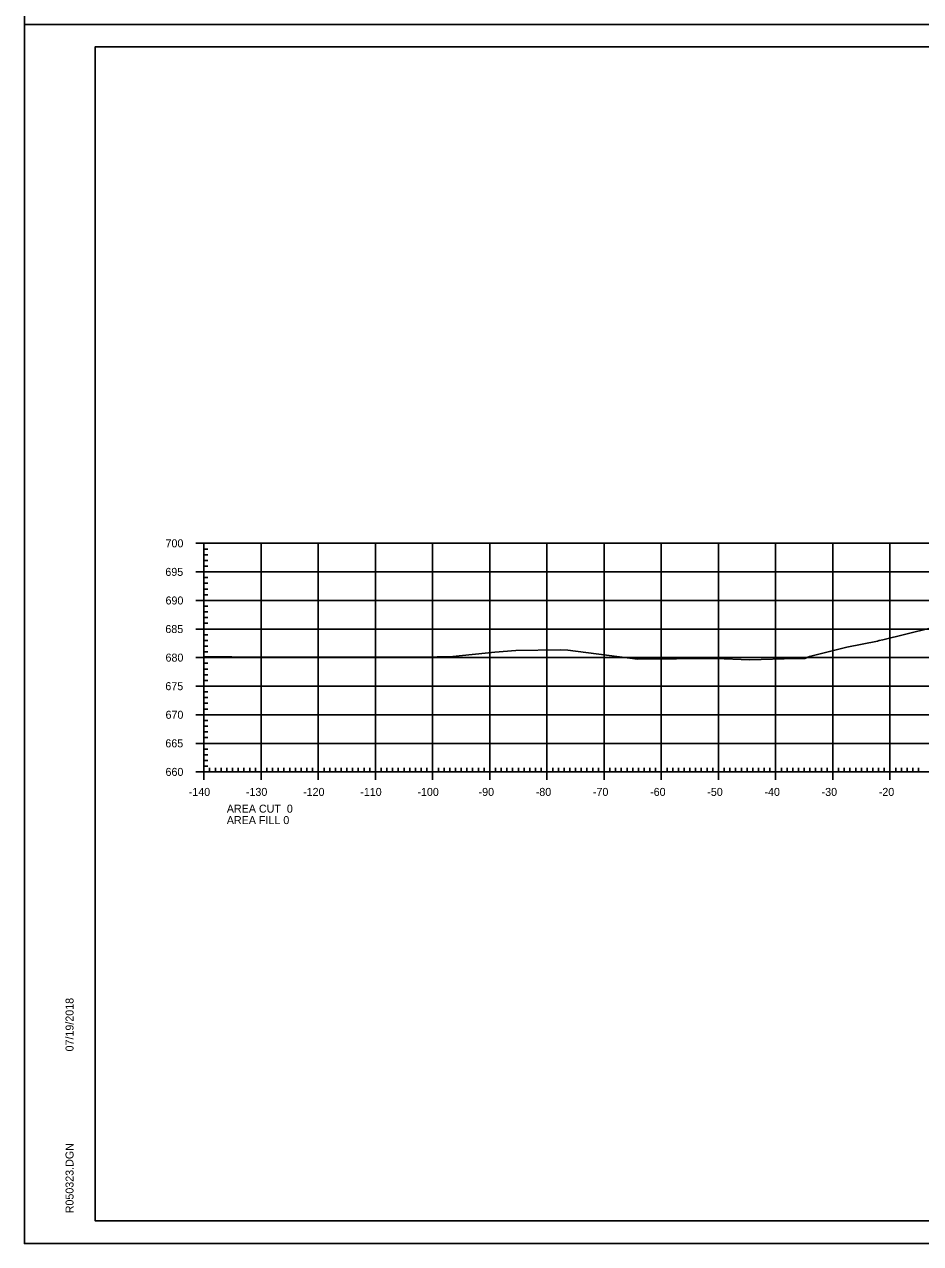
# Model space of a CAD drawing. Extents: x 1360146 to 1361431, y 631444 to 632352.
# Drawn here: x 1360146.4 to 1360303.1, y 631444.2 to 631657.5 of the extents above; entities that cross this region are included whole.
import ezdxf

# ---------------------------------------------------------------- set-up
doc = ezdxf.new("R2010")
doc.units = 0
for name, color, linetype in [('R_Axis', 7, 'Continuous'), ('R_Axis Annot', 7, 'Continuous'), ('R_Border', 7, 'Continuous'), ('R_Exist Surface', 7, 'Continuous'), ('R_Grid', 7, 'Continuous'), ('R_No Plot', 7, 'Continuous')]:
    doc.layers.add(name, color=color, linetype=linetype)

msp = doc.modelspace()

# ---------------------------------------------------------------- linework, layer by layer
at = {"layer": 'R_Axis'}
for p, q in [((1360176.37, 631566.7), (1360177.77, 631566.7)), ((1360177.77, 631526.7), (1360177.77, 631566.7)), ((1360177.77, 631565.7), (1360178.47, 631565.7)), ((1360177.77, 631564.7), (1360178.47, 631564.7)), ((1360177.77, 631563.7), (1360178.47, 631563.7)), ((1360177.77, 631562.7), (1360178.47, 631562.7)), ((1360176.37, 631561.7), (1360177.77, 631561.7)), ((1360177.77, 631560.7), (1360178.47, 631560.7)), ((1360177.77, 631559.7), (1360178.47, 631559.7)), ((1360177.77, 631558.7), (1360178.47, 631558.7)), ((1360176.37, 631556.7), (1360177.77, 631556.7)), ((1360177.77, 631557.7), (1360178.47, 631557.7)), ((1360177.77, 631555.7), (1360178.47, 631555.7)), ((1360177.77, 631554.7), (1360178.47, 631554.7)), ((1360177.77, 631553.7), (1360178.47, 631553.7)), ((1360177.77, 631552.7), (1360178.47, 631552.7)), ((1360176.37, 631551.7), (1360177.77, 631551.7)), ((1360177.77, 631550.7), (1360178.47, 631550.7)), ((1360177.77, 631549.7), (1360178.47, 631549.7)), ((1360177.77, 631548.7), (1360178.47, 631548.7)), ((1360177.77, 631547.7), (1360178.47, 631547.7)), ((1360176.37, 631546.7), (1360177.77, 631546.7)), ((1360177.77, 631545.7), (1360178.47, 631545.7)), ((1360177.77, 631544.7), (1360178.47, 631544.7)), ((1360177.77, 631543.7), (1360178.47, 631543.7)), ((1360176.37, 631541.7), (1360177.77, 631541.7)), ((1360177.77, 631542.7), (1360178.47, 631542.7)), ((1360177.77, 631540.7), (1360178.47, 631540.7)), ((1360177.77, 631539.7), (1360178.47, 631539.7)), ((1360177.77, 631538.7), (1360178.47, 631538.7)), ((1360177.77, 631537.7), (1360178.47, 631537.7)), ((1360176.37, 631536.7), (1360177.77, 631536.7)), ((1360177.77, 631535.7), (1360178.47, 631535.7)), ((1360177.77, 631534.7), (1360178.47, 631534.7)), ((1360177.77, 631533.7), (1360178.47, 631533.7)), ((1360177.77, 631532.7), (1360178.47, 631532.7)), ((1360176.37, 631531.7), (1360177.77, 631531.7)), ((1360177.77, 631530.7), (1360178.47, 631530.7)), ((1360177.77, 631529.7), (1360178.47, 631529.7)), ((1360177.77, 631528.7), (1360178.47, 631528.7)), ((1360176.37, 631526.7), (1360177.77, 631526.7)), ((1360177.77, 631527.7), (1360178.47, 631527.7)), ((1360177.77, 631526.7), (1360457.77, 631526.7)), ((1360177.77, 631525.3), (1360177.77, 631526.7)), ((1360178.77, 631526.7), (1360178.77, 631527.4)), ((1360179.77, 631526.7), (1360179.77, 631527.4)), ((1360180.77, 631526.7), (1360180.77, 631527.4)), ((1360181.77, 631526.7), (1360181.77, 631527.4)), ((1360182.77, 631526.7), (1360182.77, 631527.4)), ((1360183.77, 631526.7), (1360183.77, 631527.4)), ((1360184.77, 631526.7), (1360184.77, 631527.4)), ((1360185.77, 631526.7), (1360185.77, 631527.4)), ((1360186.77, 631526.7), (1360186.77, 631527.4)), ((1360187.77, 631525.3), (1360187.77, 631526.7)), ((1360188.77, 631526.7), (1360188.77, 631527.4)), ((1360189.77, 631526.7), (1360189.77, 631527.4)), ((1360190.77, 631526.7), (1360190.77, 631527.4)), ((1360191.77, 631526.7), (1360191.77, 631527.4)), ((1360192.77, 631526.7), (1360192.77, 631527.4)), ((1360193.77, 631526.7), (1360193.77, 631527.4)), ((1360194.77, 631526.7), (1360194.77, 631527.4)), ((1360195.77, 631526.7), (1360195.77, 631527.4)), ((1360196.77, 631526.7), (1360196.77, 631527.4)), ((1360197.77, 631525.3), (1360197.77, 631526.7)), ((1360198.77, 631526.7), (1360198.77, 631527.4)), ((1360199.77, 631526.7), (1360199.77, 631527.4)), ((1360200.77, 631526.7), (1360200.77, 631527.4)), ((1360201.77, 631526.7), (1360201.77, 631527.4)), ((1360202.77, 631526.7), (1360202.77, 631527.4)), ((1360203.77, 631526.7), (1360203.77, 631527.4)), ((1360204.77, 631526.7), (1360204.77, 631527.4)), ((1360205.77, 631526.7), (1360205.77, 631527.4)), ((1360206.77, 631526.7), (1360206.77, 631527.4)), ((1360207.77, 631525.3), (1360207.77, 631526.7)), ((1360208.77, 631526.7), (1360208.77, 631527.4)), ((1360209.77, 631526.7), (1360209.77, 631527.4)), ((1360210.77, 631526.7), (1360210.77, 631527.4)), ((1360211.77, 631526.7), (1360211.77, 631527.4)), ((1360212.77, 631526.7), (1360212.77, 631527.4)), ((1360213.77, 631526.7), (1360213.77, 631527.4)), ((1360214.77, 631526.7), (1360214.77, 631527.4)), ((1360215.77, 631526.7), (1360215.77, 631527.4)), ((1360216.77, 631526.7), (1360216.77, 631527.4)), ((1360217.77, 631525.3), (1360217.77, 631526.7)), ((1360218.77, 631526.7), (1360218.77, 631527.4)), ((1360219.77, 631526.7), (1360219.77, 631527.4)), ((1360220.77, 631526.7), (1360220.77, 631527.4)), ((1360221.77, 631526.7), (1360221.77, 631527.4)), ((1360222.77, 631526.7), (1360222.77, 631527.4)), ((1360223.77, 631526.7), (1360223.77, 631527.4)), ((1360224.77, 631526.7), (1360224.77, 631527.4)), ((1360225.77, 631526.7), (1360225.77, 631527.4)), ((1360226.77, 631526.7), (1360226.77, 631527.4)), ((1360227.77, 631525.3), (1360227.77, 631526.7)), ((1360228.77, 631526.7), (1360228.77, 631527.4)), ((1360229.77, 631526.7), (1360229.77, 631527.4)), ((1360230.77, 631526.7), (1360230.77, 631527.4)), ((1360231.77, 631526.7), (1360231.77, 631527.4)), ((1360232.77, 631526.7), (1360232.77, 631527.4)), ((1360233.77, 631526.7), (1360233.77, 631527.4)), ((1360234.77, 631526.7), (1360234.77, 631527.4)), ((1360235.77, 631526.7), (1360235.77, 631527.4)), ((1360236.77, 631526.7), (1360236.77, 631527.4)), ((1360237.77, 631525.3), (1360237.77, 631526.7)), ((1360238.77, 631526.7), (1360238.77, 631527.4)), ((1360239.77, 631526.7), (1360239.77, 631527.4)), ((1360240.77, 631526.7), (1360240.77, 631527.4)), ((1360241.77, 631526.7), (1360241.77, 631527.4)), ((1360242.77, 631526.7), (1360242.77, 631527.4)), ((1360243.77, 631526.7), (1360243.77, 631527.4)), ((1360244.77, 631526.7), (1360244.77, 631527.4)), ((1360245.77, 631526.7), (1360245.77, 631527.4)), ((1360246.77, 631526.7), (1360246.77, 631527.4)), ((1360247.77, 631525.3), (1360247.77, 631526.7)), ((1360248.77, 631526.7), (1360248.77, 631527.4)), ((1360249.77, 631526.7), (1360249.77, 631527.4)), ((1360250.77, 631526.7), (1360250.77, 631527.4)), ((1360251.77, 631526.7), (1360251.77, 631527.4)), ((1360252.77, 631526.7), (1360252.77, 631527.4)), ((1360253.77, 631526.7), (1360253.77, 631527.4)), ((1360254.77, 631526.7), (1360254.77, 631527.4)), ((1360255.77, 631526.7), (1360255.77, 631527.4)), ((1360256.77, 631526.7), (1360256.77, 631527.4)), ((1360257.77, 631525.3), (1360257.77, 631526.7)), ((1360258.77, 631526.7), (1360258.77, 631527.4)), ((1360259.77, 631526.7), (1360259.77, 631527.4)), ((1360260.77, 631526.7), (1360260.77, 631527.4)), ((1360261.77, 631526.7), (1360261.77, 631527.4)), ((1360262.77, 631526.7), (1360262.77, 631527.4)), ((1360263.77, 631526.7), (1360263.77, 631527.4)), ((1360264.77, 631526.7), (1360264.77, 631527.4)), ((1360265.77, 631526.7), (1360265.77, 631527.4)), ((1360266.77, 631526.7), (1360266.77, 631527.4)), ((1360267.77, 631525.3), (1360267.77, 631526.7)), ((1360268.77, 631526.7), (1360268.77, 631527.4)), ((1360269.77, 631526.7), (1360269.77, 631527.4)), ((1360270.77, 631526.7), (1360270.77, 631527.4)), ((1360271.77, 631526.7), (1360271.77, 631527.4)), ((1360272.77, 631526.7), (1360272.77, 631527.4)), ((1360273.77, 631526.7), (1360273.77, 631527.4)), ((1360274.77, 631526.7), (1360274.77, 631527.4)), ((1360275.77, 631526.7), (1360275.77, 631527.4)), ((1360276.77, 631526.7), (1360276.77, 631527.4)), ((1360277.77, 631525.3), (1360277.77, 631526.7)), ((1360278.77, 631526.7), (1360278.77, 631527.4)), ((1360279.77, 631526.7), (1360279.77, 631527.4)), ((1360280.77, 631526.7), (1360280.77, 631527.4)), ((1360281.77, 631526.7), (1360281.77, 631527.4)), ((1360282.77, 631526.7), (1360282.77, 631527.4)), ((1360283.77, 631526.7), (1360283.77, 631527.4)), ((1360284.77, 631526.7), (1360284.77, 631527.4)), ((1360285.77, 631526.7), (1360285.77, 631527.4)), ((1360286.77, 631526.7), (1360286.77, 631527.4)), ((1360287.77, 631525.3), (1360287.77, 631526.7)), ((1360288.77, 631526.7), (1360288.77, 631527.4)), ((1360289.77, 631526.7), (1360289.77, 631527.4)), ((1360290.77, 631526.7), (1360290.77, 631527.4)), ((1360291.77, 631526.7), (1360291.77, 631527.4)), ((1360292.77, 631526.7), (1360292.77, 631527.4)), ((1360293.77, 631526.7), (1360293.77, 631527.4)), ((1360294.77, 631526.7), (1360294.77, 631527.4)), ((1360295.77, 631526.7), (1360295.77, 631527.4)), ((1360296.77, 631526.7), (1360296.77, 631527.4)), ((1360297.77, 631525.3), (1360297.77, 631526.7)), ((1360298.77, 631526.7), (1360298.77, 631527.4)), ((1360299.77, 631526.7), (1360299.77, 631527.4)), ((1360300.77, 631526.7), (1360300.77, 631527.4)), ((1360301.77, 631526.7), (1360301.77, 631527.4)), ((1360302.77, 631526.7), (1360302.77, 631527.4))]:
    msp.add_line(p, q, dxfattribs=at)
at = {"layer": 'R_Border'}
for p, q in [((1360158.77, 631653.6), (1360474.95, 631653.6)), ((1360158.77, 631448.14), (1360158.77, 631653.6)), ((1360158.77, 631448.14), (1360158.77, 631448.14)), ((1360474.95, 631448.14), (1360158.77, 631448.14))]:
    msp.add_line(p, q, dxfattribs=at)
at = {"layer": 'R_Exist Surface'}
msp.add_lwpolyline([(1360177.77, 631546.91), (1360179.48, 631546.86), (1360182.66, 631546.84), (1360204.66, 631546.8), (1360215.8, 631546.77), (1360221.32, 631546.89), (1360228.63, 631547.66), (1360232.31, 631547.96), (1360240.08, 631548.09), (1360241.41, 631548.02), (1360253.62, 631546.42), (1360267.24, 631546.53), (1360273.25, 631546.32), (1360281.26, 631546.52), (1360282.86, 631546.56), (1360283.71, 631546.87), (1360290.22, 631548.51), (1360295.61, 631549.56), (1360295.87, 631549.67), (1360296.5, 631549.82), (1360304.82, 631551.87)], dxfattribs=at)
at = {"layer": 'R_Grid'}
for p, q in [((1360177.77, 631566.7), (1360457.77, 631566.7)), ((1360177.77, 631526.7), (1360177.77, 631566.7)), ((1360187.77, 631526.7), (1360187.77, 631566.7)), ((1360197.77, 631526.7), (1360197.77, 631566.7)), ((1360207.77, 631526.7), (1360207.77, 631566.7)), ((1360217.77, 631526.7), (1360217.77, 631566.7)), ((1360227.77, 631526.7), (1360227.77, 631566.7)), ((1360237.77, 631526.7), (1360237.77, 631566.7)), ((1360247.77, 631526.7), (1360247.77, 631566.7)), ((1360257.77, 631526.7), (1360257.77, 631566.7)), ((1360267.77, 631526.7), (1360267.77, 631566.7)), ((1360277.77, 631526.7), (1360277.77, 631566.7)), ((1360287.77, 631526.7), (1360287.77, 631566.7)), ((1360297.77, 631526.7), (1360297.77, 631566.7)), ((1360177.77, 631561.7), (1360457.77, 631561.7)), ((1360177.77, 631556.7), (1360457.77, 631556.7)), ((1360177.77, 631551.7), (1360457.77, 631551.7)), ((1360177.77, 631546.7), (1360457.77, 631546.7)), ((1360177.77, 631541.7), (1360457.77, 631541.7)), ((1360177.77, 631536.7), (1360457.77, 631536.7)), ((1360177.77, 631531.7), (1360457.77, 631531.7)), ((1360177.77, 631526.7), (1360457.77, 631526.7))]:
    msp.add_line(p, q, dxfattribs=at)
at = {"layer": 'R_No Plot'}
for p, q in [((1360146.37, 631657.5), (1360479.7, 631657.5)), ((1360146.37, 631444.17), (1360479.7, 631444.17))]:
    msp.add_line(p, q, dxfattribs=at)
for points in [[(1360146.36, 631870.84), (1360479.7, 631870.84), (1360479.7, 631657.5), (1360146.36, 631657.5)], [(1360146.36, 631657.5), (1360479.7, 631657.5), (1360479.7, 631444.16), (1360146.36, 631444.16)], [(1360392.69, 631653.6), (1360392.69, 631643.72), (1360428.42, 631643.72), (1360428.42, 631640.8), (1360451.62, 631640.8), (1360451.62, 631616.47), (1360474.95, 631616.47), (1360474.95, 631448.14), (1360158.77, 631448.14), (1360158.77, 631653.6)]]:
    msp.add_lwpolyline(points, close=True, dxfattribs=at)

# ---------------------------------------------------------------- texts
at = {"layer": 'R_Axis Annot'}
for s, p in [('700', (1360171.05, 631566)), ('695', (1360171.02, 631561)), ('690', (1360171.05, 631556)), ('685', (1360171.02, 631551)), ('680', (1360171.05, 631546)), ('675', (1360171.02, 631541)), ('670', (1360171.05, 631536)), ('665', (1360171.02, 631531)), ('660', (1360171.05, 631526)), ('-140', (1360175.11, 631522.5)), ('-130', (1360185.11, 631522.5)), ('-120', (1360195.11, 631522.5)), ('-110', (1360205.11, 631522.5)), ('-100', (1360215.11, 631522.5)), ('-90', (1360225.81, 631522.5)), ('-80', (1360235.81, 631522.5)), ('-70', (1360245.81, 631522.5)), ('-60', (1360255.81, 631522.5)), ('-50', (1360265.81, 631522.5)), ('-40', (1360275.81, 631522.5)), ('-30', (1360285.81, 631522.5)), ('-20', (1360295.81, 631522.5)), ('AREA CUT  0', (1360181.77, 631519.57)), ('AREA FILL 0', (1360181.77, 631517.57))]:
    msp.add_text(s, height=1.4, dxfattribs=at).set_placement(p)
at = {"layer": 'R_Border'}
for s, p in [('07/19/2018', (1360154.96, 631477.79)), ('R050323.DGN', (1360154.96, 631449.47))]:
    msp.add_text(s, height=1.4, rotation=90, dxfattribs=at).set_placement(p)

doc.saveas('drawing.dxf')
